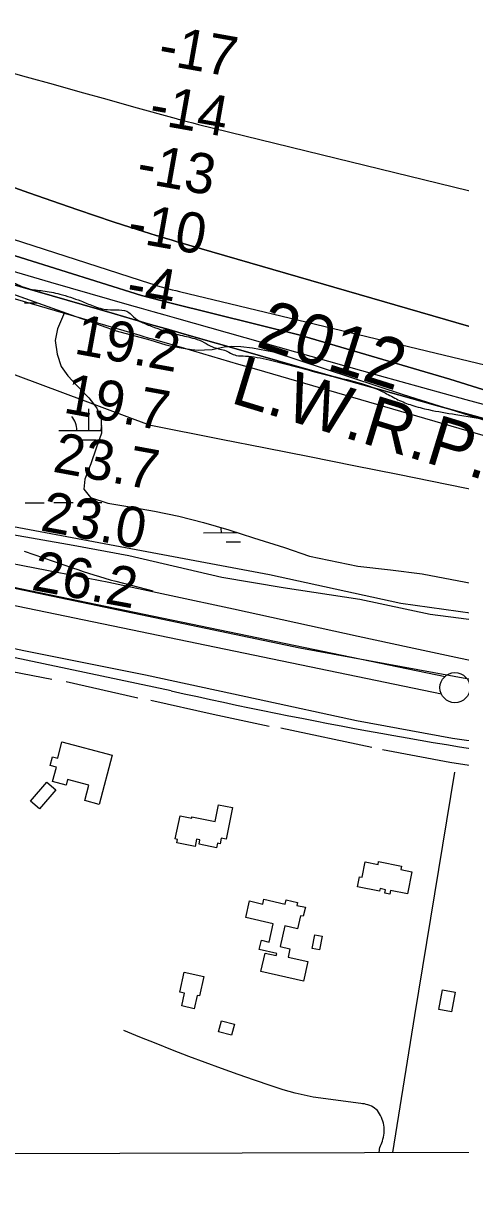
# Model space of a CAD drawing. Extents: x 3361039 to 3398939, y 576572 to 602007.
# Drawn here: x 3395141 to 3395869, y 581957 to 583922 of the extents above; entities that cross this region are included whole.
import ezdxf

# ---------------------------------------------------------------- set-up
doc = ezdxf.new("R2010")
doc.units = 0
for name, color, linetype in [('V-BLDG-OTLN', 7, 'Continuous'), ('V-DTCH-CNTR', 7, 'Continuous'), ('V-FLOD-BASE', 7, 'Continuous'), ('V-GRID-FRAM', 7, 'Continuous'), ('V-LEVE-TOET', 7, 'Continuous'), ('V-RIVR-EDGE', 7, 'Continuous'), ('V-RIVR-IDEN', 7, 'Continuous'), ('V-RIVR-RANG', 7, 'Continuous'), ('V-ROAD-CNTR', 7, 'Continuous'), ('V-SITE-VEGE', 7, 'Continuous'), ('V-SURV-LINE', 7, 'Continuous'), ('V-TOPO-DPTH', 7, 'Continuous'), ('V-TOPO-MAJR', 7, 'Continuous'), ('V-TOPO-MINR', 7, 'Continuous'), ('V-TOPO-SHOR', 7, 'Continuous'), ('V-TOPO-WATR', 7, 'Continuous'), ('V-TOPO-WATR-IDEN', 7, 'Continuous'), ('V-WETL-SWMP', 7, 'Continuous')]:
    doc.layers.add(name, color=color, linetype=linetype)

msp = doc.modelspace()

# ---------------------------------------------------------------- linework, layer by layer
at = {"layer": 'V-BLDG-OTLN'}
for points in [[(3395205, 582725.8), (3395288.9, 582703.6), (3395267.2, 582621.5), (3395243.2, 582627.9), (3395250, 582653.5), (3395214.3, 582662.9), (3395211.8, 582653.6), (3395189.3, 582659.6), (3395195.6, 582683.3), (3395185.1, 582686.1), (3395189, 582700.9), (3395197.8, 582698.6)], [(3395152.6, 582627), (3395179.9, 582658.3), (3395194.6, 582645.6), (3395167.3, 582614.2)], [(3395401.8, 582602.7), (3395421.3, 582598.7), (3395421.7, 582600.9), (3395460.3, 582593.2), (3395465.9, 582620.9), (3395489.1, 582616.3), (3395478.6, 582563.6), (3395470.5, 582565.2), (3395468.7, 582556), (3395464.4, 582556.8), (3395462.9, 582549.4), (3395433.5, 582555.3), (3395434.8, 582562.2), (3395429.3, 582563.3), (3395426.9, 582551.2), (3395396.7, 582557.2), (3395397.9, 582563.1), (3395394, 582563.9)], [(3395733, 582526.3), (3395771.2, 582518.7), (3395770.1, 582513.1), (3395788.6, 582509.3), (3395781.3, 582472.6), (3395753, 582478.3), (3395751.7, 582471.7), (3395743.4, 582473.4), (3395744.6, 582479.4), (3395735.5, 582481.2), (3395734.7, 582476.8), (3395698, 582484.2), (3395701.3, 582500.9), (3395705.4, 582500.1), (3395710.6, 582525.9), (3395732.1, 582521.6)], [(3395607.9, 582327.1), (3395536.8, 582343), (3395543.7, 582373.9), (3395562.4, 582369.7), (3395563.1, 582373), (3395534, 582379.6), (3395537.5, 582395.1), (3395550.4, 582392.2), (3395557.3, 582422.7), (3395511.3, 582432.9), (3395517.5, 582460.6), (3395540.1, 582455.5), (3395541.8, 582463.4), (3395577.1, 582455.5), (3395578.7, 582462.3), (3395597.7, 582458), (3395596.6, 582453.3), (3395610.8, 582450.1), (3395607.4, 582435.1), (3395602.9, 582436.1), (3395598, 582414.2), (3395576.4, 582419), (3395568.7, 582384.7), (3395585.1, 582381.1), (3395582, 582367.2), (3395615.2, 582359.7)], [(3395622.4, 582381.5), (3395626.6, 582404.4), (3395639, 582402.1), (3395634.7, 582379.3)], [(3395404.6, 582285.8), (3395409.3, 582307.1), (3395401.4, 582308.9), (3395408.8, 582341.9), (3395441.3, 582334.7), (3395434.1, 582302.6), (3395430.6, 582303.4), (3395425.5, 582281.2)], [(3395833.6, 582280.1), (3395839.8, 582312.8), (3395860.8, 582308.9), (3395854.6, 582276.1)], [(3395470.8, 582260.9), (3395492.5, 582255.4), (3395487.9, 582237.3), (3395466.1, 582242.8)]]:
    msp.add_lwpolyline(points, close=True, dxfattribs=at)
at = {"layer": 'V-DTCH-CNTR'}
msp.add_lwpolyline([(3395734.1, 582041.4), (3395734.1, 582042.1), (3395734.2, 582044.8), (3395734.6, 582047.5), (3395735.2, 582050.1), (3395736, 582052.7), (3395737, 582055.2), (3395738.1, 582057.6), (3395739.3, 582060.7), (3395740.3, 582063.9), (3395741.1, 582067.2), (3395741.7, 582070.5), (3395742.1, 582073.8), (3395742.3, 582077.2), (3395742.2, 582080.5), (3395742, 582083.9), (3395741.6, 582087.2), (3395740.9, 582090.5), (3395740.1, 582093.7), (3395739, 582096.9), (3395737.8, 582100), (3395736.3, 582103.1), (3395734.7, 582106), (3395732.9, 582108.8), (3395730.9, 582111.5), (3395728.7, 582113.6), (3395726.2, 582115.5), (3395723.7, 582117.2), (3395721, 582118.7), (3395718.2, 582120), (3395715.3, 582121.1), (3395712.4, 582121.9), (3395709.4, 582122.6), (3395706.3, 582123), (3395703.3, 582123.3), (3395624, 582133.8), (3395613.8, 582135.9), (3395603.7, 582138.2), (3395593.7, 582140.7), (3395583.7, 582143.4), (3395573.7, 582146.3), (3395563.8, 582149.5), (3395554, 582152.8), (3395526.3, 582162.2), (3395498.8, 582171.8), (3395471.2, 582181.5), (3395443.8, 582191.6), (3395416.5, 582201.8), (3395389.2, 582212.3), (3395362, 582223), (3395334.9, 582233.9), (3395307.9, 582245)], dxfattribs=at)
at = {"layer": 'V-FLOD-BASE'}
msp.add_line((3395601.6, 582882.1), (3396011.3, 582807), dxfattribs=at)
msp.add_lwpolyline([(3395080.1, 582990.8), (3395601.6, 582882.1)], dxfattribs=at)
at = {"layer": 'V-GRID-FRAM'}
msp.add_lwpolyline([(3365114.8, 600140.3), (3396720.3, 600227.7), (3396778.5, 582044.3), (3365157.1, 581956.9), (3365114.8, 600140.3)], dxfattribs=at)
at = {"layer": 'V-LEVE-TOET'}
for points in [[(3395954.5, 582846.6), (3395869.3, 582864.5), (3395784.2, 582882.7), (3395699.1, 582901.2), (3395595.2, 582924), (3395491.2, 582946.6), (3395387.2, 582968.9), (3395283.1, 582991.1), (3395179.8, 583011), (3395076.6, 583031.2)], [(3395962.5, 582716.4), (3395856.3, 582731.5), (3395696.4, 582760.7), (3395532, 582796), (3395344.1, 582836.7), (3395141.5, 582877), (3394929.4, 582922.4)]]:
    msp.add_lwpolyline(points, dxfattribs=at)
at = {"layer": 'V-RIVR-EDGE'}
msp.add_spline([(3387368.6, 585771), (3387389, 585767.6), (3387407.3, 585766.1), (3387418.2, 585761.7), (3387425.5, 585756.5), (3387441.6, 585752.8), (3387452.6, 585751.4), (3387462.1, 585753.9), (3387477.4, 585758.2), (3387482.9, 585759.3), (3387491.7, 585759.3), (3387502.3, 585758.2), (3387510.3, 585756.3), (3387521.6, 585753), (3387530.1, 585752.3), (3387538.5, 585752.2), (3387549.8, 585752.2), (3387558.9, 585755.5), (3387571.4, 585756.9), (3387583.4, 585757.3), (3387598.4, 585756.1), (3387629.8, 585749.5), (3387659.8, 585743.5), (3387703.3, 585736.8), (3387727.4, 585734.2), (3387739.1, 585733.5), (3387750.8, 585734.2), (3387753.7, 585731.6), (3387763.2, 585723.9), (3387774.5, 585720.6), (3387790.6, 585719.8), (3387800.1, 585721.6), (3387814, 585720.1), (3387824.6, 585720.1), (3387847.3, 585714.2), (3387884.2, 585709.4), (3387930.2, 585702.7), (3387980.6, 585701.1), (3388035.1, 585696.5), (3388076, 585694.6), (3388096.9, 585693.8), (3388120.3, 585690.5), (3388145.1, 585685.3), (3388171.8, 585682.3), (3388198.8, 585676.8), (3388222.6, 585669.4), (3388245.6, 585660.6), (3388260.9, 585655.4), (3388279.6, 585655.4), (3388291.3, 585658.3), (3388298.9, 585663.7), (3388299.3, 585666.3), (3388299, 585670.7), (3388290.6, 585674.4), (3388291.7, 585677.3), (3388293.9, 585678.4), (3388303, 585677.6), (3388318.7, 585676.5), (3388334.1, 585672.8), (3388354.1, 585663.6), (3388357.1, 585659.9), (3388363.3, 585658.1), (3388368.4, 585658.1), (3388371, 585661), (3388375.3, 585662.1), (3388379, 585661.3), (3388383, 585659.1), (3388383.7, 585654.4), (3388384.1, 585649.3), (3388389.9, 585647.4), (3388406, 585642.3), (3388468.9, 585637.7), (3388491.5, 585635.8), (3388534.6, 585628.4), (3388578.1, 585619.2), (3388610.6, 585613.6), (3388635.9, 585612.1), (3388727.9, 585599.4), (3388768.5, 585591.7), (3388822.6, 585580.9), (3388865, 585570.6), (3388906.6, 585562.8), (3388924.1, 585559.5), (3388938.8, 585562), (3388961.4, 585563.4), (3388974.2, 585560.1), (3389007.5, 585553.4), (3389018.8, 585554.5), (3389027.2, 585555.9), (3389037.1, 585555.9), (3389051.7, 585553.7), (3389061.2, 585553.3), (3389081.3, 585552.1), (3389098.1, 585551), (3389120.4, 585548.7), (3389143.4, 585546.5), (3389160.2, 585542.1), (3389200.8, 585534.7), (3389222.3, 585525.1), (3389247.2, 585519.2), (3389280.4, 585509.6), (3389307.5, 585497.8), (3389334.5, 585487.2), (3389349.5, 585483.1), (3389361.5, 585483.1), (3389382.7, 585479), (3389397, 585476.8), (3389416.7, 585468.7), (3389441.9, 585458.4), (3389464.9, 585451.4), (3389479.5, 585449.2), (3389506.2, 585446.2), (3389533.2, 585447.2), (3389558.5, 585444.2), (3389577.8, 585437.9), (3389603.4, 585431.3), (3389618.7, 585425.1), (3389639.2, 585415.1), (3389657.8, 585410.3), (3389693.2, 585404.8), (3389768.9, 585383), (3389806.5, 585373), (3389854.3, 585362.3), (3389881.7, 585358.6), (3389913.9, 585354.5), (3389953.7, 585349.3), (3390008.2, 585341.8), (3390037.8, 585336.3), (3390074.3, 585327.8), (3390128, 585312.7), (3390164.5, 585301.6), (3390200.7, 585289.8), (3390292.7, 585255.6), (3390327.1, 585241.3), (3390360.7, 585231.7), (3390404.5, 585221), (3390454.9, 585214.3), (3390483.1, 585210.5), (3390491.8, 585209.4), (3390494.4, 585207.2), (3390501.3, 585201), (3390507.9, 585200.6), (3390527.3, 585196.2), (3390545.9, 585195), (3390557.6, 585194.3), (3390574.4, 585189.8), (3390605.5, 585179.5), (3390698.6, 585148.2), (3390763.2, 585126.9), (3390811.1, 585111), (3390852.4, 585097.8), (3390900.9, 585081.6), (3390948.1, 585063.5), (3390993.7, 585048.4), (3391036.8, 585031.9), (3391070.8, 585020.1), (3391140.5, 584997.6), (3391201.5, 584974.1), (3391247.5, 584957.5), (3391310.7, 584933.6), (3391362.2, 584914.8), (3391400.6, 584900.1), (3391441.8, 584885.7), (3391505.4, 584861.1), (3391563.5, 584841.9), (3391658.8, 584807.3), (3391712.8, 584786), (3391758.8, 584767.3), (3391796.1, 584749.6), (3391880.4, 584718.3), (3391926.8, 584701.4), (3391969.2, 584685.2), (3392003.9, 584666.9), (3392040, 584650.3), (3392077.6, 584636), (3392135.7, 584613.2), (3392164.9, 584598.1), (3392196, 584583.8), (3392224.8, 584578.2), (3392263.5, 584567.9), (3392290.6, 584559.8), (3392322.7, 584546.5), (3392396.5, 584512.7), (3392439.9, 584496.2), (3392471.7, 584484.8), (3392502, 584473.3), (3392510.8, 584467.5), (3392535.2, 584458.3), (3392606.1, 584432.9), (3392632.4, 584421.5), (3392666.7, 584406.8), (3392715.6, 584386.9), (3392777.4, 584364.8), (3392827, 584348.3), (3392863.6, 584335.4), (3392897.9, 584321.8), (3392928.6, 584307.8), (3392965.4, 584294.9), (3393010, 584279.1), (3393054.6, 584263.2), (3393092.5, 584248.5), (3393195.2, 584206.6), (3393234.2, 584187.9), (3393264.5, 584173.5), (3393294.1, 584162.1), (3393336.8, 584147.4), (3393374.5, 584136.3), (3393402.2, 584127.5), (3393414.3, 584119.8), (3393435.4, 584109.1), (3393459.2, 584098.1), (3393478.9, 584087.5), (3393513.6, 584076.4), (3393541.7, 584067.2), (3393588.1, 584047.4), (3393643.2, 584028.9), (3393668.4, 584018.3), (3393699.8, 584005), (3393737.1, 583991.8), (3393781.7, 583976), (3393884.7, 583943.2), (3393927, 583928.8), (3393981.1, 583908.2), (3394043.9, 583885.4), (3394095.8, 583868.1), (3394154.9, 583847.1), (3394200.2, 583830.5), (3394247, 583816.2), (3394293, 583801.4), (3394349.6, 583781.2), (3394409.1, 583754.7), (3394451.8, 583730.5), (3394470.5, 583720.2), (3394481.8, 583715.4), (3394494.2, 583713.6), (3394502.6, 583708.1), (3394507.3, 583700.4), (3394511.3, 583697.8), (3394522.7, 583692.3), (3394557.3, 583675.8), (3394600.4, 583659.9), (3394658.1, 583638.9), (3394704.5, 583623.5), (3394760.4, 583607.6), (3394824, 583588.8), (3394867.8, 583570.8), (3394925.9, 583546.9), (3394972.2, 583528.9), (3394995.6, 583520), (3395064.7, 583504.2), (3395088.4, 583499.3), (3395120.2, 583491.6), (3395149.1, 583480.5), (3395173.2, 583476.8), (3395201.3, 583471.3), (3395236.4, 583459.9), (3395256.8, 583451.8), (3395280.9, 583445.5), (3395300.3, 583445.1), (3395316.7, 583440.7), (3395324.4, 583433.3), (3395335.3, 583426), (3395353.6, 583417.9), (3395398.9, 583403.9), (3395426.3, 583397.2), (3395442, 583391), (3395455.9, 583383.3), (3395476, 583377.8), (3395495.7, 583369.3), (3395511, 583368.2), (3395530.4, 583365.9), (3395550.5, 583361.8), (3395654.6, 583334.9), (3395704.7, 583322.4), (3395743.7, 583306.9), (3395765.3, 583295.5), (3395788.3, 583286.3), (3395816.4, 583278.9), (3395861.7, 583270.8), (3395916.2, 583261.5), (3395960.7, 583252.6), (3396008.6, 583242.6), (3396060.8, 583230.5), (3396093.4, 583222.3), (3396135.4, 583208.7), (3396170.1, 583199.8), (3396204.4, 583191.3), (3396254.8, 583177.3), (3396301.2, 583165.9), (3396364.4, 583152.9), (3396399.1, 583144.4), (3396426.9, 583138.5), (3396463.1, 583133), (3396489.8, 583132.9), (3396523.4, 583130.2), (3396607.8, 583114), (3396670.3, 583102.1), (3396708.3, 583095.4), (3396743, 583089.5), (3396775.1, 583083.9)], degree=3, dxfattribs=at)
at = {"layer": 'V-ROAD-CNTR'}
msp.add_lwpolyline([(3395387.3, 582810.5), (3394613.8, 582973.7), (3394107.2, 583074.9), (3393844.4, 583131.7)], dxfattribs=at)
msp.add_arc((3397279.3, 591299.8), 8697.6, 257.43543, 262.12976, dxfattribs=at)
at = {"layer": 'V-SITE-VEGE'}
for p, q in [((3395069.2, 583490.4), (3395220.2, 583436.8)), ((3395220.2, 583436.8), (3395295.3, 583410.1)), ((3395295.3, 583410.1), (3395351.7, 583395.2)), ((3395351.7, 583395.2), (3395378.1, 583386.8)), ((3395378.1, 583386.8), (3395391.2, 583384.1)), ((3395391.2, 583384.1), (3395407.1, 583381.2)), ((3395407.1, 583381.2), (3395421.2, 583379)), ((3395421.2, 583379), (3395432.3, 583378.2)), ((3395432.3, 583378.2), (3395442.5, 583378.3)), ((3395442.5, 583378.3), (3395455.2, 583379.3)), ((3395455.2, 583379.3), (3395465.6, 583381.3)), ((3395465.6, 583381.3), (3395475.7, 583383.4)), ((3395475.7, 583383.4), (3395487.7, 583384.6)), ((3395487.7, 583384.6), (3395503.1, 583384.1)), ((3395503.1, 583384.1), (3395522.5, 583382.1)), ((3395522.5, 583382.1), (3395557.8, 583375.2)), ((3395557.8, 583375.2), (3395773.8, 583303.9)), ((3395773.8, 583303.9), (3395960.5, 583245.5)), ((3395551, 583004), (3395061.5, 583095.3)), ((3395769.8, 582956.3), (3395551, 583004)), ((3396155.6, 582902.3), (3395769.8, 582956.3))]:
    msp.add_line(p, q, dxfattribs=at)
at = {"layer": 'V-SURV-LINE'}
for points in [[(3393819.7, 583252.9), (3395843.8, 582834.6)], [(3395837.7, 582805.3), (3393813.6, 583223.6)]]:
    msp.add_lwpolyline(points, dxfattribs=at)
msp.add_circle((3395860.3, 582815.9), 25, dxfattribs=at)
at = {"layer": 'V-TOPO-DPTH'}
for points in [[(3396774.7, 583230.3), (3396195.9, 583334.5), (3396191.7, 583335.3), (3396187.6, 583336.1), (3396183.4, 583337.1), (3396179.3, 583338), (3396126.7, 583350.6), (3396096.3, 583358), (3396066, 583365.8), (3396035.8, 583374), (3396005.7, 583382.5), (3395395.3, 583559.2), (3395387, 583561.6), (3395378.7, 583564.1), (3395370.4, 583566.6), (3395362.2, 583569.2), (3395319.7, 583582.5), (3395290.2, 583592), (3395260.9, 583601.6), (3395231.6, 583611.5), (3395202.4, 583621.6), (3395149.8, 583640.1), (3395094.5, 583659.7)], [(3395094.5, 583659.7), (3395149.8, 583640.1), (3395202.4, 583621.6), (3395231.6, 583611.5), (3395260.9, 583601.6), (3395290.2, 583592), (3395319.7, 583582.5), (3395362.2, 583569.2), (3395370.4, 583566.6), (3395378.7, 583564.1), (3395387, 583561.6), (3395395.3, 583559.2), (3396005.7, 583382.5), (3396035.8, 583374), (3396066, 583365.8), (3396096.3, 583358), (3396126.7, 583350.6), (3396179.3, 583338), (3396183.4, 583337.1), (3396187.6, 583336.1), (3396191.7, 583335.3), (3396195.9, 583334.5), (3396774.7, 583230.3)], [(3396775.1, 583107.7), (3396334.9, 583200.2), (3396210.6, 583223.5), (3396188.5, 583227.8), (3396170.7, 583232.9), (3396109.4, 583249.2), (3395851.6, 583329.9), (3395599.8, 583403.8), (3395387.1, 583456.2), (3395337.7, 583469.1), (3395000.8, 583574.7)], [(3395000.8, 583574.7), (3395337.7, 583469.1), (3395387.1, 583456.2), (3395599.8, 583403.8), (3395851.6, 583329.9), (3396109.4, 583249.2), (3396170.7, 583232.9), (3396188.5, 583227.8), (3396210.6, 583223.5), (3396334.9, 583200.2), (3396775.1, 583107.7)], [(3396775.2, 583071.2), (3396215.1, 583181.8), (3396189.7, 583188.1), (3396164.3, 583194.5), (3396138.9, 583201.1), (3396113.6, 583208), (3395827.3, 583286.6), (3395748.1, 583308.5), (3395668.9, 583330.6), (3395589.9, 583353), (3395510.8, 583375.5), (3395413.1, 583403.5), (3395383, 583412.2), (3395352.8, 583420.9), (3395322.7, 583429.6), (3395292.5, 583438.3), (3395001.1, 583522.6)]]:
    msp.add_lwpolyline(points, dxfattribs=at)
at = {"layer": 'V-TOPO-MAJR'}
msp.add_lwpolyline([(3395141.9, 583043), (3395222.3, 583015.5), (3395231.3, 583012.5), (3395240.3, 583009.5), (3395249.3, 583006.6), (3395258.3, 583003.7), (3395267.3, 583001), (3395276.4, 582998.3), (3395285.5, 582995.7), (3395294.6, 582993.3), (3395356.6, 582976.9)], dxfattribs=at)
at = {"layer": 'V-TOPO-MINR'}
for points in [[(3394593.7, 583989.2), (3395145.5, 583833.3), (3395190.2, 583820.8), (3395234.9, 583808.2), (3395279.6, 583795.8), (3395324.4, 583783.4), (3395395.2, 583763.9), (3395404.5, 583761.3), (3395413.9, 583758.8), (3395423.4, 583756.4), (3395432.8, 583754), (3395637.3, 583703.8), (3395735.1, 583679.9), (3395833, 583656), (3395930.9, 583632.1), (3396028.8, 583608.4), (3396205.7, 583565.5), (3396215.1, 583563.2), (3396224.5, 583560.8), (3396233.9, 583558.4), (3396243.3, 583555.9), (3396282.8, 583545.2), (3396774.1, 583403.1)], [(3394837.4, 583655), (3395352.5, 583489), (3395358.5, 583487.2), (3395364.5, 583485.3), (3395370.5, 583483.6), (3395376.5, 583481.8), (3395382.5, 583480.2), (3395388.6, 583478.6), (3395394.7, 583477.1), (3395400.7, 583475.6), (3396125.2, 583302.1), (3396152.5, 583295.7), (3396179.9, 583289.4), (3396207.3, 583283.4), (3396234.8, 583277.5), (3396384.8, 583245.9), (3396487.4, 583224.6), (3396590, 583203.4), (3396692.7, 583182.7), (3396774.9, 583166.2)], [(3395094.5, 583659.7), (3395149.8, 583640.1), (3395202.4, 583621.6), (3395231.6, 583611.5), (3395260.9, 583601.6), (3395290.2, 583592), (3395319.7, 583582.5), (3395362.2, 583569.2), (3395370.4, 583566.6), (3395378.7, 583564.1), (3395387, 583561.6), (3395395.3, 583559.2), (3396005.7, 583382.5), (3396035.8, 583374), (3396066, 583365.8), (3396096.3, 583358), (3396126.7, 583350.6), (3396179.3, 583338), (3396183.4, 583337.1), (3396187.6, 583336.1), (3396191.7, 583335.3), (3396195.9, 583334.5), (3396774.7, 583230.3)], [(3394733.6, 583577.7), (3395334.6, 583402.9), (3395341.7, 583400.8), (3395348.8, 583398.8), (3395355.9, 583396.7), (3395363, 583394.6), (3395409.1, 583381.2), (3395439.2, 583372.4), (3395469.3, 583363.6), (3395499.5, 583354.8), (3395529.6, 583346.1), (3396106.8, 583178.4), (3396133, 583170.9), (3396159.2, 583163.6), (3396185.5, 583156.5), (3396775.3, 583028.8)], [(3394511.2, 583566.1), (3395350.3, 583253.7), (3395470.7, 583230), (3395544.3, 583215.5), (3395617.9, 583200.9), (3395691.4, 583186.1), (3395764.9, 583171.2), (3396103, 583102.4), (3396125.3, 583097.8), (3396147.6, 583093.2), (3396169.8, 583088.4), (3396192.1, 583083.6), (3396344.3, 583050.2), (3396442.8, 583029.2), (3396541.5, 583009.1), (3396640.4, 582990.2), (3396739.5, 582972.1), (3396775.5, 582965.7)], [(3395001.1, 583522.6), (3395292.5, 583438.3), (3395322.7, 583429.6), (3395352.8, 583420.9), (3395383, 583412.2), (3395413.1, 583403.5), (3395510.8, 583375.5), (3395589.9, 583353), (3395668.9, 583330.6), (3395748.1, 583308.5), (3395827.3, 583286.6), (3396113.6, 583208), (3396138.9, 583201.1), (3396164.3, 583194.5), (3396189.7, 583188.1), (3396215.1, 583181.8), (3396775.2, 583071.2)], [(3395100.4, 583516), (3395185.8, 583491.4), (3395317.3, 583453.6), (3395337, 583447.9), (3395356.7, 583442.3), (3395376.4, 583436.7), (3395396.1, 583431.1), (3395733.8, 583335.8), (3395806, 583315.7), (3395878.3, 583295.8), (3395950.7, 583276.4), (3396023.2, 583257.3), (3396142.5, 583226.2), (3396155.4, 583222.9), (3396168.4, 583219.6), (3396181.4, 583216.6), (3396194.4, 583213.6), (3396775.1, 583093.4)]]:
    msp.add_lwpolyline(points, dxfattribs=at)
at = {"layer": 'V-TOPO-SHOR'}
for p, q in [((3395122.1, 582842.6), (3395188.3, 582829.9)), ((3395212, 582825.9), (3395331.3, 582799)), ((3395569.9, 582749.2), (3395721.9, 582717))]:
    msp.add_line(p, q, dxfattribs=at)
for points in [[(3395353.2, 582795), (3395457, 582772), (3395550.4, 582751.5)], [(3395739.7, 582712.7), (3395851.5, 582692), (3395891.5, 582685.5), (3395905.8, 582683)], [(3395859.5, 582675.3), (3395793, 582269.9), (3395756.1, 582041.5)]]:
    msp.add_lwpolyline(points, dxfattribs=at)
at = {"layer": 'V-TOPO-WATR'}
msp.add_lwpolyline([(3396775.1, 583107.7), (3396334.9, 583200.2), (3396210.6, 583223.5), (3396188.5, 583227.8), (3396170.7, 583232.9), (3396109.4, 583249.2), (3395851.6, 583329.9), (3395599.8, 583403.8), (3395387.1, 583456.2), (3395337.7, 583469.1), (3395000.8, 583574.7)], dxfattribs=at)
at = {"layer": 'V-WETL-SWMP'}
for p, q in [((3395069.2, 583490.5), (3395209.1, 583440.8)), ((3395142.4, 583456.6), (3395164.4, 583456.7)), ((3395209.1, 583440.8), (3395197.6, 583413.3)), ((3395197.6, 583413.3), (3395193.9, 583394)), ((3395193.9, 583394), (3395196.8, 583371.5)), ((3395196.8, 583371.5), (3395203.7, 583351)), ((3395203.7, 583351), (3395214.6, 583335.1)), ((3395214.6, 583335.1), (3395229.8, 583319.2)), ((3395229.8, 583319.2), (3395249.7, 583298.5)), ((3395249.7, 583298.5), (3395263.3, 583281.4)), ((3395249.9, 583244.3), (3395249.8, 583280.3)), ((3395263.3, 583281.4), (3395270.6, 583262.8)), ((3395270.6, 583262.8), (3395270.8, 583239.9)), ((3395199.9, 583244.2), (3395270.7, 583244.3)), ((3395270.8, 583239.9), (3395262.2, 583214.8)), ((3395237.9, 583228.8), (3395261.9, 583228.9)), ((3395262.2, 583214.8), (3395253.3, 583188.8)), ((3395253.3, 583188.8), (3395243.2, 583162.9)), ((3395243.2, 583162.9), (3395241.5, 583146.4)), ((3395241.5, 583146.4), (3395252.7, 583132.8)), ((3395143.4, 583123.9), (3395175.4, 583124)), ((3395191.4, 583124.1), (3395223.4, 583124.1)), ((3395239.4, 583124.2), (3395271.4, 583124.3)), ((3395252.7, 583132.8), (3395281.4, 583123.1)), ((3395281.4, 583123.1), (3395311.3, 583118.1)), ((3395311.3, 583118.1), (3395359.4, 583110.1)), ((3395359.4, 583110.1), (3395399.9, 583101.4)), ((3395399.9, 583101.4), (3395441.2, 583091.1)), ((3395441.2, 583091.1), (3395483.2, 583078.9)), ((3395483.2, 583078.9), (3395524.1, 583065.5)), ((3395223.4, 583052.4), (3395113.2, 583072.1)), ((3395440.8, 583074), (3395497.6, 583074.2)), ((3395478.9, 583058.7), (3395502.9, 583058.8)), ((3395490.8, 583074.1), (3395490.8, 583076.4)), ((3395524.1, 583065.5), (3395576, 583049.2)), ((3395316.7, 583035.7), (3395223.4, 583052.4)), ((3395576, 583049.2), (3395617.6, 583034.9)), ((3395471.7, 582999.5), (3395316.7, 583035.7)), ((3395617.6, 583034.9), (3395698.3, 583018.4)), ((3395574, 582981.9), (3395471.7, 582999.5)), ((3395698.3, 583018.4), (3395753, 583012.3)), ((3395753, 583012.3), (3395805.8, 583005.5)), ((3395805.8, 583005.5), (3395922.3, 582983)), ((3395701.5, 582962.5), (3395574, 582981.9)), ((3395818.8, 582937.6), (3395701.5, 582962.5)), ((3395991.6, 582915), (3395818.8, 582937.6))]:
    msp.add_line(p, q, dxfattribs=at)
for centre, start, end in [((3395194.6, 583244.6), 359.3865, 40.9302), ((3395305.1, 583244.9), 167.6669, 180.9301), ((3395435.6, 583074.5), 359.3865, 13.6456)]:
    msp.add_arc(centre, 35.2, start, end, dxfattribs=at)

# ---------------------------------------------------------------- texts
at = {"layer": 'V-RIVR-IDEN'}
msp.add_text(' 2012', height=83, rotation=342.4968, dxfattribs=at).set_placement((3395497.2, 583393.8))
at = {"layer": 'V-RIVR-RANG'}
for s, rotation, p in [('-17', 349.8902, (3395363.1, 583855.1)), ('-14', 349.8902, (3395348.1, 583756.1)), ('-13', 349.8902, (3395327, 583658.3)), ('-10', 349.8902, (3395311.5, 583559.5)), ('-4', 349.8902, (3395309.8, 583458.2)), ('19.2', 349.6083, (3395223.4, 583372.7)), ('19.7', 349.6083, (3395205.6, 583274.3)), ('23.7', 349.6083, (3395187.8, 583175.9)), ('23.0', 349.6083, (3395167.1, 583078)), ('26.2', 349.6083, (3395152.2, 582979.1))]:
    msp.add_text(s, height=67, rotation=rotation, dxfattribs=at).set_placement(p)
at = {"layer": 'V-TOPO-WATR-IDEN'}
msp.add_text('L.W.R.P.', height=83, rotation=343.0168, dxfattribs=at).set_placement((3395484, 583291))

doc.saveas('drawing.dxf')
